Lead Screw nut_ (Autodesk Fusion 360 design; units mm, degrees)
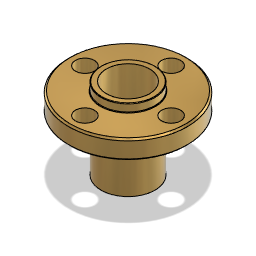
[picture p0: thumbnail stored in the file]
sketch "Sketch1" plane through (0, 0, 0) normal (0, 1, 0) x axis (1, 0, 0)
  circle C1 centre (0, 0) radius 5
  point P1 (0, 0)
  point P2 (0, 0)
  coincident P1 P2
  dimension "d1" diameter C1 = 10
extrude "Extrude1" new body sketch "Sketch1" along normal blind 10
sketch "Sketch2" plane through (0, 10, 0) normal (0, 1, 0) x axis (-1, 0, 0)
  circle C1 centre (0, 0) radius 5
  circle C2 centre (0, 0) radius 11
  point P2 (0, 0)
  point P4 (0, 0)
  coincident P2 P4
  dimension "d4" diameter C2 = 22
extrude "Extrude2" add sketch "Sketch2" along normal blind 3.5
sketch "Sketch3" plane through (0, 13.5, 0) normal (0, 1, 0) x axis (-1, 0, 0)
  circle C1 centre (0, 0) radius 11
  circle C2 centre (0, 0) radius 5
  concentric C1 C2
  dimension "d7" diameter C2 = 10
extrude "Extrude3" add sketch "Sketch3" profile of C2 along normal blind 1.5 (= "-13.50 mm + 15 mm")
sketch "Sketch4" plane through (0, 13.5, 0) normal (0, 1, 0) x axis (-1, 0, 0)
  circle C1 centre (0, 0) radius 5
  circle C2 centre (0, 0) radius 11
  circle C3 centre (0, 0) radius 8
  circle C4 centre (-8, 0) radius 1.75
  point P1 (0, 0)
  point P3 (0, 0)
  point P4 (-8, 0)
  coincident P1 P3
  coincident C3 P4
  dimension "d10" diameter C3 = 16
  dimension "d11" diameter C4 = 3.5
extrude "Extrude4" cut sketch "Sketch4" profile of C3 C4 against normal blind 3.5
circular_pattern "C-Pattern1" TotalAngle 360
chamfer "Chamfer1" distance 0.3
sketch "Sketch5" plane through (0, 15, 0) normal (0, 1, 0) x axis (-1, 0, 0)
  circle C1 centre (0, 0) radius 5
  circle C2 centre (0, 0) radius 4
  concentric C1 C2
  dimension "d17" diameter C2 = 8
extrude "Extrude5" cut sketch "Sketch5" profile of C2 against normal blind 15
fillet "Fillet1" radius 0.1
